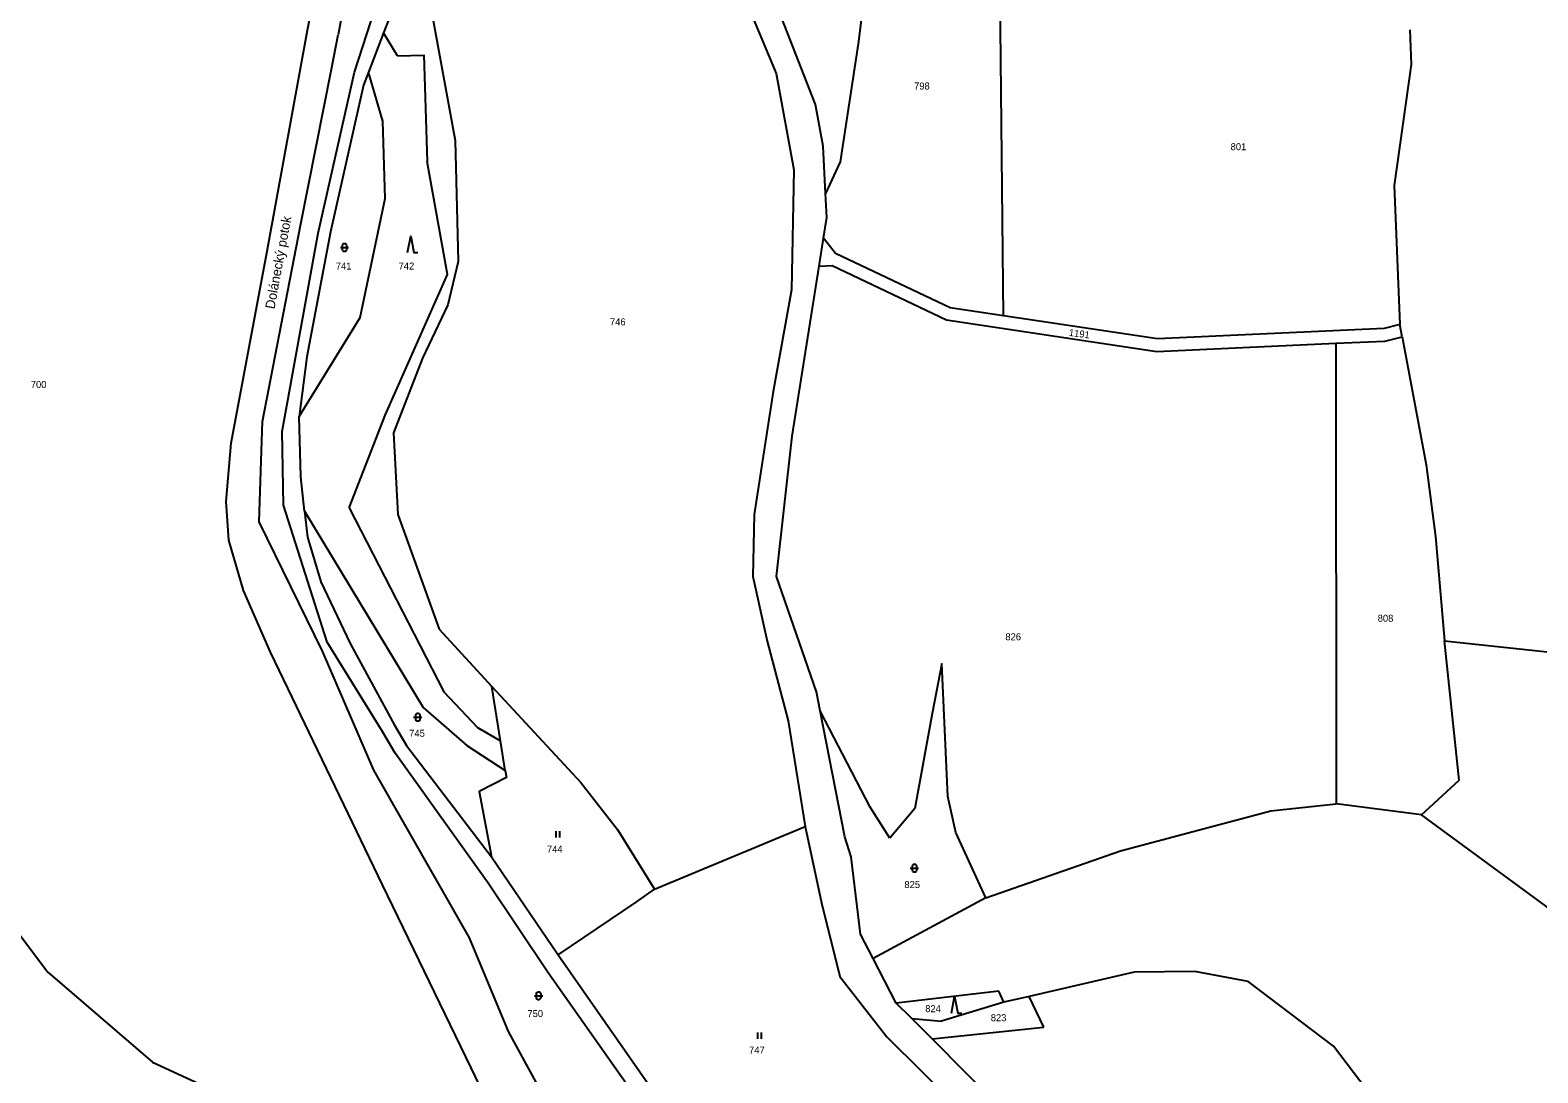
# Model space of a CAD drawing. Extents: x -812394 to -807601, y -1013097 to -1009266.
# Drawn here: x -809418.3 to -809053.2, y -1011159.4 to -1010907 of the extents above; entities that cross this region are included whole.
import ezdxf

# ---------------------------------------------------------------- set-up
doc = ezdxf.new("R2010")
doc.units = 0
for name, color, linetype in [('Default', 7, 'Continuous'), ('KN_HRANICE', 7, 'Continuous'), ('KN_KULTURY', 7, 'Continuous'), ('KN_PARCELY', 7, 'Continuous')]:
    doc.layers.add(name, color=color, linetype=linetype)

# ---------------------------------------------------------------- blocks, each defined once
blk = doc.blocks.new('306')
at = {"layer": 'Default'}
for p, q in [((-0.5, 1.5), (-0.5, 0)), ((0.5, 0), (0.5, 1.5))]:
    blk.add_line(p, q, dxfattribs=at)
blk = doc.blocks.new('308')
at = {"layer": 'Default'}
blk.add_lwpolyline([(-0.75, 0), (0, 4), (0.75, 0), (1.75, 0)], dxfattribs=at)
blk = doc.blocks.new('316')
at = {"layer": 'Default'}
for points in [[(-1, 1), (0.27, 1), (1, 1)], [(-0.5, 1.5), (-0.4, 1.79), (-0.15, 1.97), (0.16, 1.97), (0.41, 1.79), (0.51, 1.5), (0.51, 0.5), (0.41, 0.21), (0.16, 0.03), (-0.15, 0.03), (-0.4, 0.21), (-0.5, 0.5), (-0.5, 1.5)]]:
    blk.add_lwpolyline(points, dxfattribs=at)

msp = doc.modelspace()

# ---------------------------------------------------------------- linework, layer by layer
at = {"layer": 'KN_HRANICE'}
for p, q in [((-809264.15, -1010854.13), (-809237.69, -1010917.44)), ((-809351.15, -1010907.01), (-809342.76, -1010863.71)), ((-809211.78, -1010863.69), (-809217.85, -1010910.29)), ((-809228.17, -1010924.96), (-809242.93, -1010887.17)), ((-809328.19, -1010895.88), (-809332.71, -1010907.64)), ((-809182.59, -1010976.12), (-809183.47, -1010897.59)), ((-809342.56, -1010901.99), (-809343.75, -1010908.11)), ((-809339.74, -1010917.13), (-809334.79, -1010901.69)), ((-809321.27, -1010901.54), (-809315.42, -1010933.7)), ((-809360.75, -1010959.55), (-809351.15, -1010907.01)), ((-809332.71, -1010907.64), (-809336.38, -1010917.18)), ((-809329.36, -1010913.21), (-809332.71, -1010907.64)), ((-809084.22, -1010906.93), (-809083.93, -1010915.3)), ((-809217.85, -1010910.29), (-809222.2, -1010938.83)), ((-809348.56, -1010956.1), (-809339.74, -1010917.13)), ((-809083.93, -1010915.3), (-809088.03, -1010944.58)), ((-809337.58, -1010920.29), (-809345.55, -1010955.82)), ((-809336.38, -1010917.18), (-809337.58, -1010920.29)), ((-809237.69, -1010917.44), (-809233.39, -1010940.77)), ((-809226.26, -1010935.05), (-809228.17, -1010924.96)), ((-809315.42, -1010933.7), (-809314.64, -1010962.96)), ((-809225.71, -1010946.53), (-809226.26, -1010935.05)), ((-809222.2, -1010938.83), (-809225.71, -1010946.53)), ((-809233.39, -1010940.77), (-809233.99, -1010969.84)), ((-809088.03, -1010944.58), (-809086.63, -1010978.22)), ((-809225.43, -1010952.31), (-809225.71, -1010946.53)), ((-809226.21, -1010957.33), (-809225.43, -1010952.31)), ((-809357.31, -1011004.14), (-809348.56, -1010956.1)), ((-809345.55, -1010955.82), (-809351.29, -1010986.02)), ((-809369.66, -1011006.98), (-809360.75, -1010959.55)), ((-809227.25, -1010964.08), (-809226.21, -1010957.33)), ((-809223.26, -1010961.02), (-809226.21, -1010957.33)), ((-809314.64, -1010962.96), (-809317.18, -1010973.46)), ((-809233.82, -1011005.3), (-809227.25, -1010964.08)), ((-809227.25, -1010964.08), (-809224.09, -1010963.94)), ((-809224.09, -1010963.94), (-809196.42, -1010977.07)), ((-809195.54, -1010974.17), (-809223.26, -1010961.02)), ((-809233.99, -1010969.84), (-809238.41, -1010994.42)), ((-809317.18, -1010973.46), (-809323.27, -1010986.38)), ((-809182.59, -1010976.12), (-809195.54, -1010974.17)), ((-809196.42, -1010977.07), (-809145.53, -1010984.73)), ((-809145.37, -1010981.72), (-809182.59, -1010976.12)), ((-809086.63, -1010978.22), (-809090.45, -1010979.23)), ((-809086.08, -1010981.18), (-809086.63, -1010978.22)), ((-809145.53, -1010984.73), (-809102.18, -1010982.77)), ((-809090.45, -1010979.23), (-809145.37, -1010981.72)), ((-809102.18, -1010982.77), (-809090.32, -1010982.23)), ((-809102.18, -1010982.77), (-809102.05, -1011094.31)), ((-809090.32, -1010982.23), (-809086.08, -1010981.18)), ((-809086.08, -1010981.18), (-809080.31, -1011012.17)), ((-809351.29, -1010986.02), (-809353.14, -1011000.49)), ((-809323.27, -1010986.38), (-809330.28, -1011004.43)), ((-809238.41, -1010994.42), (-809243.03, -1011024.27)), ((-809356.99, -1011021.98), (-809357.31, -1011004.14)), ((-809330.28, -1011004.43), (-809329.24, -1011024.22)), ((-809370.8, -1011021.05), (-809369.66, -1011006.98)), ((-809237.57, -1011039.2), (-809233.82, -1011005.3)), ((-809080.31, -1011012.17), (-809078.02, -1011029.54)), ((-809346.38, -1011055.16), (-809356.99, -1011021.98)), ((-809351.85, -1011023.44), (-809351.16, -1011029.72)), ((-809329.24, -1011024.22), (-809319.27, -1011052)), ((-809243.03, -1011024.27), (-809243.29, -1011039.21)), ((-809351.16, -1011029.72), (-809347.94, -1011040.55)), ((-809078.02, -1011029.54), (-809075.88, -1011054.83)), ((-809347.94, -1011040.55), (-809340.8, -1011055.43)), ((-809243.29, -1011039.21), (-809239.88, -1011054.88)), ((-809227.91, -1011067.2), (-809237.57, -1011039.2)), ((-809319.27, -1011052), (-809306.54, -1011065.84)), ((-809332.9, -1011076.93), (-809346.38, -1011055.16)), ((-809340.8, -1011055.43), (-809330.11, -1011075.2)), ((-809239.88, -1011054.88), (-809234.8, -1011074.21)), ((-809072.31, -1011088.53), (-809075.88, -1011054.83)), ((-809075.88, -1011054.83), (-808951.36, -1011068.01)), ((-809197.56, -1011060.27), (-809199.87, -1011072.38)), ((-809196.14, -1011092.51), (-809197.56, -1011060.27)), ((-809306.54, -1011065.84), (-809284.98, -1011089.13)), ((-809304.41, -1011078.99), (-809306.54, -1011065.84)), ((-809227.01, -1011071.76), (-809227.91, -1011067.2)), ((-809214.9, -1011095.05), (-809227.01, -1011071.76)), ((-809221.02, -1011102.26), (-809227.01, -1011071.76)), ((-809199.87, -1011072.38), (-809204.08, -1011095.41)), ((-809329.89, -1011082), (-809332.9, -1011076.93)), ((-809330.11, -1011075.2), (-809327.19, -1011080.12)), ((-809234.8, -1011074.21), (-809230.64, -1011099.78)), ((-809327.19, -1011080.12), (-809306.61, -1011107.09)), ((-809303.25, -1011086.19), (-809304.41, -1011078.99)), ((-809307.36, -1011113.45), (-809329.89, -1011082)), ((-809303.25, -1011086.19), (-809302.97, -1011087.89)), ((-809081.38, -1011096.96), (-809072.31, -1011088.53)), ((-809284.98, -1011089.13), (-809276.12, -1011100.51)), ((-809210.17, -1011102.63), (-809214.9, -1011095.05)), ((-809204.08, -1011095.41), (-809210.17, -1011102.63)), ((-809194.17, -1011101.23), (-809196.14, -1011092.51)), ((-809081.38, -1011096.96), (-809102.05, -1011094.31)), ((-809048.99, -1011120.76), (-809081.38, -1011096.96)), ((-809276.12, -1011100.51), (-809267.11, -1011114.96)), ((-809267.11, -1011114.96), (-809230.64, -1011099.78)), ((-809230.64, -1011099.78), (-809226.7, -1011118.26)), ((-809219.52, -1011107.12), (-809221.02, -1011102.26)), ((-809186.94, -1011117), (-809194.17, -1011101.23)), ((-809437.7, -1011103.69), (-809413.98, -1011135.02)), ((-809306.61, -1011107.09), (-809290.45, -1011130.86)), ((-809217.26, -1011125.81), (-809219.52, -1011107.12)), ((-809292.88, -1011135.16), (-809307.36, -1011113.45)), ((-809271.53, -1011118.12), (-809267.11, -1011114.96)), ((-809186.94, -1011117), (-809214.18, -1011131.75)), ((-809290.45, -1011130.86), (-809271.53, -1011118.12)), ((-809226.7, -1011118.26), (-809222.24, -1011136.1)), ((-809214.18, -1011131.75), (-809217.26, -1011125.81)), ((-809290.45, -1011130.86), (-809244.33, -1011196.74)), ((-809208.59, -1011142.51), (-809214.18, -1011131.75)), ((-809413.98, -1011135.02), (-809388.65, -1011156.86)), ((-809249.48, -1011196.8), (-809292.88, -1011135.16)), ((-809222.24, -1011136.1), (-809210.85, -1011150.65)), ((-809151.01, -1011135.04), (-809176.38, -1011140.9)), ((-809136.28, -1011134.9), (-809151.01, -1011135.04)), ((-809123.42, -1011137.33), (-809136.28, -1011134.9)), ((-809183.77, -1011139.63), (-809208.59, -1011142.51)), ((-809182.51, -1011142.31), (-809183.77, -1011139.63)), ((-809102.71, -1011152.94), (-809123.42, -1011137.33)), ((-809204.83, -1011146.28), (-809208.59, -1011142.51)), ((-809182.51, -1011142.31), (-809197.6, -1011146.91)), ((-809176.38, -1011140.9), (-809182.51, -1011142.31)), ((-809172.88, -1011148.32), (-809176.38, -1011140.9)), ((-809199.91, -1011151.21), (-809204.83, -1011146.28)), ((-809204.83, -1011146.28), (-809197.6, -1011146.91)), ((-809210.85, -1011150.65), (-809177.04, -1011184.11)), ((-809199.91, -1011151.21), (-809172.88, -1011148.32)), ((-809180.8, -1011170.37), (-809199.91, -1011151.21)), ((-809083.49, -1011178.16), (-809102.71, -1011152.94)), ((-809388.65, -1011156.86), (-809355.08, -1011172.25))]:
    msp.add_line(p, q, dxfattribs=at)
for points in [[(-809362.27, -1011008.78), (-809362.03, -1011001.71), (-809352.87, -1010954.23), (-809345.36, -1010916.43), (-809343.75, -1010908.11)], [(-809329.36, -1010913.21), (-809322.98, -1010913.02), (-809322.16, -1010938.75)], [(-809353.14, -1011000.49), (-809338.36, -1010976.54), (-809332.32, -1010947.69), (-809332.87, -1010928.98), (-809336.38, -1010917.18)], [(-809341.02, -1011022.61), (-809332.28, -1011000.05), (-809317.23, -1010966.13), (-809322.16, -1010938.75)], [(-809351.85, -1011023.44), (-809352.77, -1011015.12), (-809353.14, -1011000.49)], [(-809311.9, -1011126.69), (-809335.1, -1011086.13), (-809347.52, -1011057.28), (-809362.87, -1011025.99), (-809362.27, -1011008.78)], [(-809294.96, -1011192.54), (-809311.49, -1011158.23), (-809332.98, -1011113.92), (-809360.07, -1011057.57), (-809366.67, -1011042.66), (-809370.18, -1011030.46), (-809370.8, -1011021.05)], [(-809341.02, -1011022.61), (-809318.1, -1011067.16), (-809309.99, -1011075.82), (-809304.41, -1011078.99)], [(-809351.85, -1011023.44), (-809323.11, -1011070.98), (-809312.59, -1011080.19), (-809303.25, -1011086.19)], [(-809302.97, -1011087.89), (-809309.58, -1011091.26), (-809306.61, -1011107.09)], [(-809186.94, -1011117), (-809154.28, -1011105.63), (-809117.9, -1011095.99), (-809102.05, -1011094.31)], [(-809272.89, -1011193.49), (-809282.21, -1011186.49), (-809302.51, -1011149.43), (-809311.9, -1011126.69)]]:
    msp.add_lwpolyline(points, dxfattribs=at)

# ---------------------------------------------------------------- block references
at = {"layer": 'KN_KULTURY'}
for name, p in [('308', (-809326.16, -1010960.82)), ('316', (-809342.18, -1010960.59)), ('316', (-809324.45, -1011074.33)), ('306', (-809290.53, -1011102.4)), ('316', (-809204.19, -1011110.87)), ('316', (-809295.18, -1011141.73)), ('308', (-809194.47, -1011144.96)), ('306', (-809241.72, -1011151.16))]:
    msp.add_blockref(name, p, dxfattribs=at)

# ---------------------------------------------------------------- texts
at = {"layer": 'KN_PARCELY'}
for s, p in [('798', (-809204.27, -1010921.34)), ('801', (-809127.63, -1010936.03)), ('741', (-809344.29, -1010964.93)), ('742', (-809329.09, -1010964.93)), ('746', (-809277.92, -1010978.45)), ('700', (-809418.14, -1010993.61)), ('808', (-809092.02, -1011050.2)), ('826', (-809182.17, -1011054.68)), ('745', (-809326.52, -1011078.04)), ('744', (-809293.18, -1011106.11)), ('825', (-809206.62, -1011114.67)), ('824', (-809201.57, -1011144.72)), ('750', (-809297.9, -1011145.91)), ('823', (-809185.71, -1011146.91)), ('747', (-809244.23, -1011154.74))]:
    msp.add_text(s, height=1.7, dxfattribs=at).set_placement(p)
for s, height, rotation, p in [('Dolánecký potok', 2.3, 79.527, (-809359.15, -1010974.61)), ('1191', 1.7, 352.484, (-809166.87, -1010980.97))]:
    msp.add_text(s, height=height, rotation=rotation, dxfattribs=at).set_placement(p)

doc.saveas('drawing.dxf')
